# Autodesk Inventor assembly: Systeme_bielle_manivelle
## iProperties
Shininess: 64.0
Length Units: 11269
Angle Units: 11279
Time Units: 11290
Mass Units: 11283
Length Display Precision: 3
Angle Display Precision: 2
Compacted: True
Created: 2003-11
Part Number: Systeme_bielle_manivelle
Document SubType Name: Assembly
Designer: Flavien MARTY
Density: 0.0
Volumn: 0.0
Area: 0.0
PropertySet Name: Model Information
Control State: 0
Master: False
Checked Out: False
Author: Flavien MARTY
